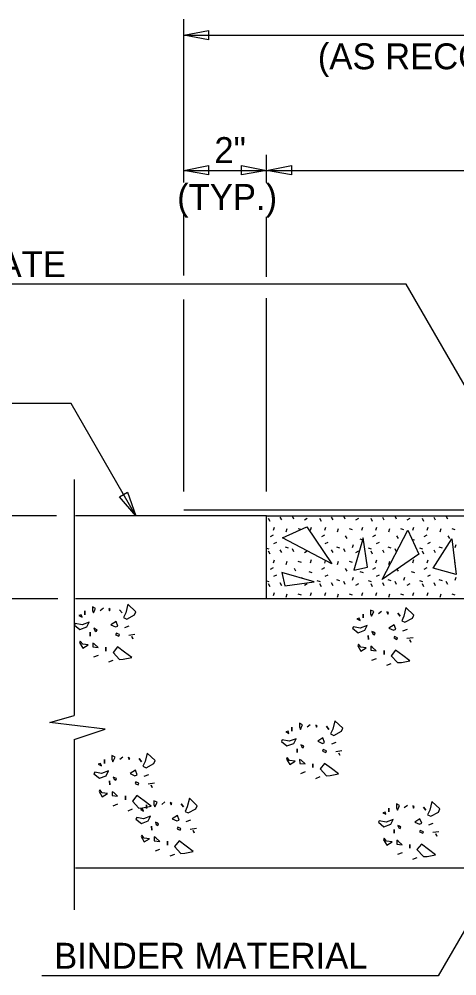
# Model space of a CAD drawing. Extents: x 0 to 11.3, y 0 to 7.8.
# Drawn here: x 2.009 to 2.89, y 1.64 to 3.565 of the extents above; entities that cross this region are included whole.
import ezdxf

# ---------------------------------------------------------------- set-up
doc = ezdxf.new("R2010")
doc.units = 0
for name, color, linetype in [('BRDG_ANNO_General-Notes', 7, 'Continuous'), ('BRDG_BASE_Obj-Line', 7, 'Continuous'), ('BRDG_BASE_Pattern', 7, 'Continuous')]:
    doc.layers.add(name, color=color, linetype=linetype)

msp = doc.modelspace()

# ---------------------------------------------------------------- linework, layer by layer
at = {"layer": 'BRDG_ANNO_General-Notes'}
for p, q in [((2.3401, 3.2366), (2.3401, 3.5652)), ((2.3401, 3.5326), (2.3901, 3.542)), ((2.3401, 3.5326), (4.3401, 3.5326)), ((2.3901, 3.5232), (2.3401, 3.5326)), ((2.3901, 3.542), (2.3901, 3.5232)), ((2.5067, 3.2366), (2.5067, 3.2919)), ((2.3401, 3.2609), (2.3901, 3.2703)), ((2.3401, 3.2609), (2.5067, 3.2609)), ((2.3901, 3.2516), (2.3401, 3.2609)), ((2.3901, 3.2703), (2.3901, 3.2516)), ((2.4567, 3.2516), (2.4567, 3.2703)), ((2.4567, 3.2703), (2.5067, 3.2609)), ((2.5067, 3.2609), (2.4567, 3.2516)), ((2.5067, 3.2609), (2.5567, 3.2703)), ((2.5067, 3.2609), (4.1734, 3.2609)), ((2.5567, 3.2516), (2.5067, 3.2609)), ((2.5567, 3.2703), (2.5567, 3.2516)), ((2.3401, 3.0491), (2.3401, 3.1718)), ((2.5067, 3.0464), (2.5067, 3.1674)), ((2.788, 3.0317), (1.4643, 3.0317)), ((3.1414, 2.4195), (2.788, 3.0317)), ((2.5067, 2.6145), (2.5067, 3.0039)), ((2.3401, 2.6145), (2.3401, 3.0012)), ((2.1133, 2.7918), (1.623, 2.7918)), ((2.244, 2.5654), (2.1133, 2.7918)), ((2.2109, 2.604), (2.2271, 2.6133)), ((2.244, 2.5654), (2.2109, 2.604)), ((2.2271, 2.6133), (2.244, 2.5654)), ((2.0841, 2.5654), (1.4941, 2.5654)), ((2.0867, 2.3987), (1.4941, 2.3987)), ((3.2567, 2.3401), (2.8525, 1.6399)), ((2.8525, 1.6399), (2.0544, 1.6399))]:
    msp.add_line(p, q, dxfattribs=at)
at = {"layer": 'BRDG_BASE_Obj-Line'}
for p, q in [((2.1195, 2.6385), (2.1195, 2.164)), ((2.5067, 2.5654), (2.122, 2.5654)), ((4.3401, 2.5769), (2.3401, 2.5769)), ((2.5067, 2.3987), (2.5067, 2.5654)), ((2.5067, 2.5654), (4.1734, 2.5654)), ((2.5095, 2.5654), (2.5112, 2.5648)), ((2.5103, 2.5611), (2.5133, 2.5552)), ((2.5337, 2.5631), (2.5368, 2.5573)), ((2.562, 2.5589), (2.559, 2.5648)), ((2.6127, 2.5654), (2.6144, 2.5648)), ((2.6134, 2.5611), (2.6165, 2.5552)), ((2.6369, 2.5631), (2.6399, 2.5573)), ((2.6652, 2.5589), (2.6622, 2.5648)), ((2.7158, 2.5654), (2.7176, 2.5648)), ((2.7166, 2.5611), (2.7196, 2.5552)), ((2.7401, 2.5631), (2.7431, 2.5573)), ((2.7684, 2.5589), (2.7654, 2.5648)), ((2.819, 2.5654), (2.8207, 2.5648)), ((2.8198, 2.5611), (2.8228, 2.5552)), ((2.8433, 2.5631), (2.8463, 2.5573)), ((2.8716, 2.5589), (2.8685, 2.5648)), ((2.522, 2.5424), (2.5199, 2.5361)), ((2.5888, 2.5602), (2.5829, 2.5572)), ((2.5964, 2.5425), (2.5944, 2.5362)), ((2.6252, 2.5424), (2.6231, 2.5361)), ((2.6919, 2.5602), (2.6861, 2.5572)), ((2.6996, 2.5425), (2.6976, 2.5362)), ((2.7283, 2.5424), (2.7262, 2.5361)), ((2.7951, 2.5602), (2.7893, 2.5572)), ((2.8028, 2.5425), (2.8008, 2.5362)), ((2.8315, 2.5424), (2.8294, 2.5361)), ((2.5199, 2.5265), (2.514, 2.5234)), ((2.5466, 2.5336), (2.5486, 2.5399)), ((2.5758, 2.5379), (2.5706, 2.5396)), ((2.6231, 2.5265), (2.6171, 2.5234)), ((2.6497, 2.5336), (2.6518, 2.5399)), ((2.6691, 2.5198), (2.666, 2.5257)), ((2.6801, 2.5376), (2.6738, 2.5396)), ((2.7262, 2.5265), (2.7203, 2.5234)), ((2.7529, 2.5336), (2.755, 2.5399)), ((2.7722, 2.5198), (2.7692, 2.5257)), ((2.7832, 2.5376), (2.777, 2.5396)), ((2.8294, 2.5265), (2.8235, 2.5234)), ((2.8561, 2.5336), (2.8582, 2.5399)), ((2.8754, 2.5198), (2.8724, 2.5257)), ((2.8864, 2.5376), (2.8802, 2.5396)), ((2.5216, 2.5098), (2.5274, 2.5129)), ((2.5513, 2.5008), (2.5449, 2.5028)), ((2.6247, 2.5098), (2.6306, 2.5129)), ((2.6544, 2.5008), (2.6481, 2.5028)), ((2.6798, 2.5018), (2.6819, 2.5081)), ((2.6948, 2.5191), (2.7004, 2.5173)), ((2.7279, 2.5098), (2.7338, 2.5129)), ((2.7576, 2.5008), (2.7513, 2.5028)), ((2.7995, 2.5186), (2.8043, 2.5171)), ((2.8311, 2.5098), (2.837, 2.5129)), ((2.8608, 2.5008), (2.8545, 2.5028)), ((2.8862, 2.5018), (2.8882, 2.5081)), ((2.5067, 2.5005), (2.5112, 2.4991)), ((2.5103, 2.4954), (2.5133, 2.4894)), ((2.5337, 2.4974), (2.5368, 2.4916)), ((2.562, 2.4931), (2.559, 2.4991)), ((2.5888, 2.4945), (2.5829, 2.4915)), ((2.6369, 2.4974), (2.6399, 2.4916)), ((2.6652, 2.4931), (2.6622, 2.4991)), ((2.6919, 2.4945), (2.6861, 2.4915)), ((2.7112, 2.5011), (2.7176, 2.4991)), ((2.7166, 2.4954), (2.7196, 2.4894)), ((2.7401, 2.4974), (2.7431, 2.4916)), ((2.7683, 2.4933), (2.7654, 2.4991)), ((2.8144, 2.5011), (2.8207, 2.4991)), ((2.8198, 2.4954), (2.8228, 2.4894)), ((2.8433, 2.4974), (2.8463, 2.4916)), ((2.522, 2.4767), (2.5199, 2.4704)), ((2.5466, 2.4679), (2.5486, 2.4742)), ((2.5769, 2.4719), (2.5706, 2.4739)), ((2.5964, 2.4768), (2.5944, 2.4705)), ((2.6249, 2.4761), (2.6231, 2.4704)), ((2.6497, 2.4679), (2.6518, 2.4742)), ((2.6801, 2.4719), (2.6738, 2.4739)), ((2.7283, 2.4767), (2.7262, 2.4704)), ((2.7529, 2.4679), (2.755, 2.4742)), ((2.8028, 2.4768), (2.8008, 2.4705)), ((2.8315, 2.4767), (2.8294, 2.4704)), ((2.8864, 2.4719), (2.8853, 2.4722)), ((2.5199, 2.4607), (2.514, 2.4577)), ((2.5216, 2.4441), (2.5274, 2.4471)), ((2.5659, 2.4541), (2.5629, 2.4599)), ((2.5916, 2.4534), (2.5979, 2.4514)), ((2.6231, 2.4607), (2.6171, 2.4577)), ((2.6247, 2.4441), (2.6306, 2.4471)), ((2.6691, 2.4541), (2.666, 2.4599)), ((2.6948, 2.4534), (2.7011, 2.4514)), ((2.7262, 2.4607), (2.7203, 2.4577)), ((2.7279, 2.4441), (2.7338, 2.4471)), ((2.7722, 2.4541), (2.7699, 2.4586)), ((2.798, 2.4534), (2.8043, 2.4514)), ((2.8294, 2.4607), (2.8235, 2.4577)), ((2.8311, 2.4441), (2.837, 2.4471)), ((2.5067, 2.4348), (2.5112, 2.4333)), ((2.5103, 2.4296), (2.5133, 2.4237)), ((2.5337, 2.4317), (2.5368, 2.4258)), ((2.5779, 2.44), (2.5787, 2.4423)), ((2.5888, 2.4287), (2.5829, 2.4257)), ((2.6081, 2.4354), (2.6144, 2.4333)), ((2.6134, 2.4296), (2.6165, 2.4237)), ((2.6369, 2.4317), (2.6399, 2.4258)), ((2.6544, 2.4351), (2.6481, 2.4371)), ((2.6652, 2.4274), (2.6622, 2.4333)), ((2.6798, 2.436), (2.6819, 2.4423)), ((2.6919, 2.4287), (2.6861, 2.4257)), ((2.7112, 2.4354), (2.7176, 2.4333)), ((2.7166, 2.4296), (2.7196, 2.4237)), ((2.7401, 2.4317), (2.7431, 2.4258)), ((2.7576, 2.4351), (2.7513, 2.4371)), ((2.7684, 2.4274), (2.7654, 2.4333)), ((2.783, 2.436), (2.7851, 2.4423)), ((2.7951, 2.4287), (2.7893, 2.4257)), ((2.8144, 2.4354), (2.8207, 2.4333)), ((2.8198, 2.4296), (2.8228, 2.4237)), ((2.8433, 2.4317), (2.8463, 2.4258)), ((2.8608, 2.4351), (2.8545, 2.4371)), ((2.8716, 2.4274), (2.8685, 2.4333)), ((2.8862, 2.436), (2.8882, 2.4423)), ((2.522, 2.411), (2.5199, 2.4047)), ((2.5466, 2.4021), (2.5486, 2.4084)), ((2.5769, 2.4061), (2.5706, 2.4081)), ((2.5964, 2.411), (2.5944, 2.4048)), ((2.6252, 2.411), (2.6231, 2.4047)), ((2.6497, 2.4021), (2.6518, 2.4084)), ((2.6801, 2.4061), (2.6738, 2.4081)), ((2.6996, 2.411), (2.6976, 2.4048)), ((2.7283, 2.411), (2.7262, 2.4047)), ((2.7529, 2.4021), (2.755, 2.4084)), ((2.7832, 2.4061), (2.777, 2.4081)), ((2.8028, 2.411), (2.8008, 2.4048)), ((2.8315, 2.411), (2.8294, 2.4047)), ((2.8561, 2.4021), (2.8582, 2.4084)), ((2.8864, 2.4061), (2.8802, 2.4081)), ((3.2567, 2.3987), (2.122, 2.3987)), ((2.0709, 2.1501), (2.1195, 2.164)), ((2.182, 2.1362), (2.0709, 2.1501)), ((2.1195, 2.1154), (2.182, 2.1362)), ((2.1195, 2.1154), (2.1195, 1.773)), ((3.2567, 1.857), (2.122, 1.857))]:
    msp.add_line(p, q, dxfattribs=at)
for points in [[(2.5067, 2.5654), (4.1734, 2.5654), (4.1734, 2.3987), (2.5067, 2.3987)], [(2.6381, 2.4693), (2.5388, 2.5211), (2.5877, 2.5433)], [(2.7393, 2.4378), (2.7911, 2.537), (2.8133, 2.4882)], [(2.7015, 2.5212), (2.6826, 2.4562), (2.7099, 2.4625)], [(2.842, 2.4604), (2.8797, 2.5191), (2.8881, 2.4479)], [(2.6023, 2.4329), (2.5374, 2.4518), (2.5436, 2.4245)]]:
    msp.add_lwpolyline(points, close=True, dxfattribs=at)
at = {"layer": 'BRDG_BASE_Pattern'}
for p, q in [((2.1722, 2.3754), (2.1784, 2.3803)), ((2.7319, 2.3689), (2.7381, 2.3737)), ((2.2215, 2.341), (2.2305, 2.3441)), ((2.7812, 2.3345), (2.7902, 2.3376)), ((2.2295, 2.3257), (2.242, 2.3274)), ((2.7892, 2.3192), (2.8017, 2.3209)), ((2.1593, 2.2816), (2.1684, 2.2851)), ((2.1892, 2.2716), (2.1982, 2.2751)), ((2.719, 2.2751), (2.7281, 2.2786)), ((2.7489, 2.2651), (2.7579, 2.2685)), ((2.5887, 2.1411), (2.5949, 2.146)), ((2.638, 2.1068), (2.647, 2.1099)), ((2.2112, 2.0761), (2.2175, 2.081)), ((2.646, 2.0915), (2.6585, 2.0932)), ((2.2606, 2.0418), (2.2696, 2.0449)), ((2.5758, 2.0474), (2.5849, 2.0509)), ((2.6057, 2.0373), (2.6147, 2.0408)), ((2.2685, 2.0265), (2.281, 2.0282)), ((2.1984, 1.9824), (2.2074, 1.9859)), ((2.2958, 1.9851), (2.3021, 1.9899)), ((2.784, 1.9785), (2.7902, 1.9834)), ((2.2283, 1.9723), (2.2373, 1.9758)), ((2.3452, 1.9507), (2.3542, 1.9538)), ((2.8333, 1.9442), (2.8423, 1.9473)), ((2.3531, 1.9354), (2.3656, 1.9371)), ((2.8413, 1.9289), (2.8537, 1.9306)), ((2.283, 1.8913), (2.292, 1.8948)), ((2.7711, 1.8848), (2.7802, 1.8883)), ((2.3129, 1.8812), (2.3219, 1.8847)), ((2.801, 1.8747), (2.81, 1.8782))]:
    msp.add_line(p, q, dxfattribs=at)
for points in [[(2.2236, 2.3705), (2.2191, 2.3611), (2.2257, 2.358), (2.2409, 2.3664), (2.2437, 2.3726), (2.2278, 2.3876)], [(2.1413, 2.3667), (2.1413, 2.3743)], [(2.1566, 2.3751), (2.1583, 2.3702), (2.1614, 2.3764), (2.1628, 2.3795), (2.1566, 2.3827)], [(2.1892, 2.3789), (2.1909, 2.3743), (2.1923, 2.3774), (2.1923, 2.3774), (2.1923, 2.3774), (2.1923, 2.3774), (2.1892, 2.3789), (2.1892, 2.3789)], [(2.2159, 2.3702), (2.2111, 2.3764)], [(2.7163, 2.3685), (2.718, 2.3636), (2.7211, 2.3699), (2.7225, 2.373), (2.7163, 2.3761)], [(2.7489, 2.3723), (2.7506, 2.3678), (2.752, 2.3709), (2.752, 2.3709), (2.752, 2.3709), (2.752, 2.3709), (2.7489, 2.3723), (2.7489, 2.3723)], [(2.7756, 2.3636), (2.7708, 2.3699)], [(2.7833, 2.364), (2.7788, 2.3546), (2.7854, 2.3515), (2.8006, 2.3598), (2.8034, 2.3661), (2.7874, 2.381)], [(2.1201, 2.3459), (2.1312, 2.3368), (2.1451, 2.342), (2.1496, 2.3514), (2.1357, 2.3462), (2.1218, 2.349)], [(2.1291, 2.3649), (2.1354, 2.3618), (2.1336, 2.3664)], [(2.1934, 2.3462), (2.2028, 2.342), (2.2072, 2.3438), (2.2038, 2.3528)], [(2.6888, 2.3584), (2.6951, 2.3553), (2.6933, 2.3598)], [(2.701, 2.3602), (2.701, 2.3678)], [(2.152, 2.3236), (2.1517, 2.3313)], [(2.1611, 2.3347), (2.1642, 2.333), (2.1642, 2.333), (2.1656, 2.3361), (2.1656, 2.3361), (2.1624, 2.3379), (2.1624, 2.3379), (2.1593, 2.3393), (2.1593, 2.3393), (2.1611, 2.3347)], [(2.2062, 2.3251), (2.2093, 2.3236), (2.2107, 2.3268), (2.2107, 2.3268), (2.2076, 2.3282), (2.2076, 2.3282), (2.2045, 2.3295), (2.2045, 2.3295), (2.2045, 2.3295), (2.2031, 2.3264)], [(2.6798, 2.3394), (2.6909, 2.3303), (2.7048, 2.3355), (2.7093, 2.3449), (2.6954, 2.3397), (2.6815, 2.3425)], [(2.7208, 2.3282), (2.7239, 2.3265), (2.7239, 2.3265), (2.7253, 2.3296), (2.7253, 2.3296), (2.7221, 2.3314), (2.7221, 2.3314), (2.719, 2.3328), (2.719, 2.3328), (2.7208, 2.3282)], [(2.7531, 2.3397), (2.7624, 2.3355), (2.7669, 2.3373), (2.7635, 2.3463)], [(2.1305, 2.3105), (2.1371, 2.2997), (2.1476, 2.3063), (2.1368, 2.3077), (2.1319, 2.3136)], [(2.2374, 2.3181), (2.2357, 2.3226)], [(2.7117, 2.3171), (2.7114, 2.3248)], [(2.7659, 2.3185), (2.769, 2.3171), (2.7704, 2.3203), (2.7704, 2.3203), (2.7673, 2.3217), (2.7673, 2.3217), (2.7642, 2.323), (2.7642, 2.323), (2.7642, 2.323), (2.7628, 2.3199)], [(2.7971, 2.3116), (2.7954, 2.3161)], [(2.1572, 2.3018), (2.168, 2.3007), (2.168, 2.3007), (2.1601, 2.308), (2.1569, 2.3097)], [(2.1836, 2.2934), (2.1836, 2.3011)], [(2.1979, 2.2907), (2.2107, 2.2768), (2.2184, 2.2771), (2.2354, 2.2806), (2.2211, 2.2914), (2.2069, 2.3018)], [(2.6902, 2.304), (2.6968, 2.2932), (2.7072, 2.2998), (2.6965, 2.3011), (2.6916, 2.3071)], [(2.7169, 2.2953), (2.7277, 2.2942), (2.7277, 2.2942), (2.7197, 2.3015), (2.7166, 2.3032)], [(2.7433, 2.2869), (2.7433, 2.2946)], [(2.7576, 2.2842), (2.7704, 2.2703), (2.7781, 2.2706), (2.7951, 2.2741), (2.7808, 2.2848), (2.7666, 2.2953)], [(2.5578, 2.1325), (2.5578, 2.1401)], [(2.5731, 2.1408), (2.5748, 2.1359), (2.5779, 2.1422), (2.5793, 2.1453), (2.5731, 2.1484)], [(2.6057, 2.1446), (2.6074, 2.1401), (2.6089, 2.1432), (2.6089, 2.1432), (2.6089, 2.1432), (2.6089, 2.1432), (2.6057, 2.1446), (2.6057, 2.1446)], [(2.6324, 2.1359), (2.6276, 2.1422)], [(2.6401, 2.1363), (2.6356, 2.1269), (2.6422, 2.1238), (2.6574, 2.1321), (2.6602, 2.1384), (2.6443, 2.1533)], [(2.5456, 2.1307), (2.5519, 2.1276), (2.5502, 2.1321)], [(2.6099, 2.112), (2.6193, 2.1078), (2.6237, 2.1096), (2.6203, 2.1186)], [(2.5366, 2.1117), (2.5477, 2.1026), (2.5616, 2.1078), (2.5661, 2.1172), (2.5522, 2.112), (2.5383, 2.1148)], [(2.5776, 2.1005), (2.5807, 2.0988), (2.5807, 2.0988), (2.5821, 2.1019), (2.5821, 2.1019), (2.579, 2.1036), (2.579, 2.1036), (2.5758, 2.1051), (2.5758, 2.1051), (2.5776, 2.1005)], [(2.1956, 2.0758), (2.1973, 2.0709), (2.2005, 2.0772), (2.2019, 2.0803), (2.1956, 2.0834)], [(2.2283, 2.0796), (2.23, 2.0751), (2.2314, 2.0782), (2.2314, 2.0782), (2.2314, 2.0782), (2.2314, 2.0782), (2.2283, 2.0796), (2.2283, 2.0796)], [(2.2627, 2.0713), (2.2581, 2.0619), (2.2647, 2.0588), (2.28, 2.0671), (2.2828, 2.0734), (2.2668, 2.0883)], [(2.547, 2.0762), (2.5536, 2.0655), (2.5641, 2.0721), (2.5533, 2.0734), (2.5484, 2.0794)], [(2.5685, 2.0894), (2.5682, 2.0971)], [(2.6227, 2.0908), (2.6258, 2.0894), (2.6272, 2.0926), (2.6272, 2.0926), (2.6241, 2.094), (2.6241, 2.094), (2.621, 2.0953), (2.621, 2.0953), (2.621, 2.0953), (2.6196, 2.0922)], [(2.654, 2.0839), (2.6522, 2.0884)], [(2.1682, 2.0657), (2.1744, 2.0626), (2.1727, 2.0671)], [(2.1804, 2.0675), (2.1804, 2.0751)], [(2.255, 2.0709), (2.2502, 2.0772)], [(2.5737, 2.0676), (2.5845, 2.0665), (2.5845, 2.0665), (2.5766, 2.0738), (2.5734, 2.0755)], [(2.6002, 2.0592), (2.6002, 2.0669)], [(2.6144, 2.0565), (2.6272, 2.0426), (2.6349, 2.0429), (2.6519, 2.0464), (2.6377, 2.0571), (2.6234, 2.0676)], [(2.1592, 2.0467), (2.1703, 2.0376), (2.1842, 2.0428), (2.1887, 2.0522), (2.1748, 2.047), (2.1609, 2.0498)], [(2.2324, 2.047), (2.2418, 2.0428), (2.2463, 2.0446), (2.2429, 2.0536)], [(2.1911, 2.0244), (2.1908, 2.0321)], [(2.2002, 2.0355), (2.2033, 2.0338), (2.2033, 2.0338), (2.2046, 2.0369), (2.2046, 2.0369), (2.2015, 2.0386), (2.2015, 2.0386), (2.1984, 2.0401), (2.1984, 2.0401), (2.2002, 2.0355)], [(2.2453, 2.0258), (2.2484, 2.0244), (2.2498, 2.0276), (2.2498, 2.0276), (2.2467, 2.029), (2.2467, 2.029), (2.2435, 2.0303), (2.2435, 2.0303), (2.2435, 2.0303), (2.2421, 2.0272)], [(2.2765, 2.0189), (2.2748, 2.0234)], [(2.1696, 2.0112), (2.1762, 2.0005), (2.1866, 2.0071), (2.1758, 2.0084), (2.171, 2.0144)], [(2.1963, 2.0026), (2.2071, 2.0015), (2.2071, 2.0015), (2.1991, 2.0088), (2.196, 2.0105)], [(2.2369, 1.9915), (2.2498, 1.9776), (2.2574, 1.9779), (2.2744, 1.9814), (2.2602, 1.9921), (2.246, 2.0026)], [(2.2227, 1.9942), (2.2227, 2.0019)], [(2.2649, 1.9764), (2.2649, 1.984)], [(2.2802, 1.9847), (2.2819, 1.9798), (2.2851, 1.9861), (2.2865, 1.9892), (2.2802, 1.9923)], [(2.3129, 1.9885), (2.3146, 1.984), (2.316, 1.9871), (2.316, 1.9871), (2.316, 1.9871), (2.316, 1.9871), (2.3129, 1.9885), (2.3129, 1.9885)], [(2.3396, 1.9798), (2.3347, 1.9861)], [(2.3472, 1.9802), (2.3427, 1.9708), (2.3493, 1.9677), (2.3646, 1.976), (2.3673, 1.9823), (2.3514, 1.9972)], [(2.7683, 1.9782), (2.7701, 1.9733), (2.7732, 1.9796), (2.7746, 1.9827), (2.7683, 1.9858)], [(2.8354, 1.9737), (2.8308, 1.9643), (2.8374, 1.9612), (2.8527, 1.9695), (2.8555, 1.9758), (2.8395, 1.9907)], [(2.2528, 1.9746), (2.259, 1.9715), (2.2573, 1.976)], [(2.7409, 1.9681), (2.7471, 1.965), (2.7454, 1.9695)], [(2.7531, 1.9699), (2.7531, 1.9775)], [(2.801, 1.982), (2.8027, 1.9775), (2.8041, 1.9806), (2.8041, 1.9806), (2.8041, 1.9806), (2.8041, 1.9806), (2.801, 1.982), (2.801, 1.982)], [(2.8277, 1.9733), (2.8229, 1.9796)], [(2.2437, 1.9556), (2.2548, 1.9465), (2.2687, 1.9517), (2.2733, 1.9611), (2.2594, 1.9559), (2.2455, 1.9587)], [(2.2847, 1.9444), (2.2879, 1.9427), (2.2879, 1.9427), (2.2892, 1.9458), (2.2892, 1.9458), (2.2861, 1.9476), (2.2861, 1.9476), (2.283, 1.949), (2.283, 1.949), (2.2847, 1.9444)], [(2.317, 1.9559), (2.3264, 1.9517), (2.3309, 1.9535), (2.3274, 1.9625)], [(2.7319, 1.9491), (2.743, 1.94), (2.7569, 1.9452), (2.7614, 1.9546), (2.7475, 1.9494), (2.7336, 1.9522)], [(2.8052, 1.9494), (2.8145, 1.9452), (2.819, 1.947), (2.8156, 1.956)], [(2.2757, 1.9333), (2.2754, 1.941)], [(2.3298, 1.9347), (2.333, 1.9333), (2.3344, 1.9365), (2.3344, 1.9365), (2.3312, 1.9379), (2.3312, 1.9379), (2.3281, 1.9392), (2.3281, 1.9392), (2.3281, 1.9392), (2.3267, 1.9361)], [(2.3611, 1.9278), (2.3594, 1.9323)], [(2.7638, 1.9268), (2.7635, 1.9345)], [(2.7729, 1.9379), (2.776, 1.9362), (2.776, 1.9362), (2.7773, 1.9393), (2.7773, 1.9393), (2.7742, 1.941), (2.7742, 1.941), (2.7711, 1.9424), (2.7711, 1.9424), (2.7729, 1.9379)], [(2.818, 1.9282), (2.8211, 1.9268), (2.8225, 1.9299), (2.8225, 1.9299), (2.8194, 1.9314), (2.8194, 1.9314), (2.8162, 1.9327), (2.8162, 1.9327), (2.8162, 1.9327), (2.8148, 1.9296)], [(2.8492, 1.9212), (2.8475, 1.9258)], [(2.2542, 1.9202), (2.2608, 1.9094), (2.2712, 1.916), (2.2604, 1.9173), (2.2556, 1.9233)], [(2.2809, 1.9115), (2.2917, 1.9104), (2.2917, 1.9104), (2.2837, 1.9177), (2.2806, 1.9194)], [(2.3073, 1.9031), (2.3073, 1.9108)], [(2.3215, 1.9004), (2.3344, 1.8865), (2.342, 1.8868), (2.359, 1.8903), (2.3448, 1.901), (2.3306, 1.9115)], [(2.7423, 1.9136), (2.7489, 1.9029), (2.7593, 1.9095), (2.7485, 1.9108), (2.7437, 1.9168)], [(2.769, 1.9049), (2.7798, 1.9039), (2.7798, 1.9039), (2.7718, 1.9112), (2.7687, 1.9129)], [(2.7954, 1.8966), (2.7954, 1.9043)], [(2.8096, 1.8939), (2.8225, 1.8799), (2.8302, 1.8803), (2.8471, 1.8838), (2.8329, 1.8945), (2.8187, 1.9049)]]:
    msp.add_lwpolyline(points, close=True, dxfattribs=at)

# ---------------------------------------------------------------- texts
at = {"layer": 'BRDG_ANNO_General-Notes'}
for s, height, p in [('(AS RECOMMENDED BY MANUFACTURER)', 0.052083, (2.61, 3.4643)), ('2"', 0.05208, (2.4018, 3.2756)), ('(TYP.)', 0.05208, (2.3269, 3.1813)), ('BRIDGING PLATE', 0.052083, (1.5186, 3.046)), ('BINDER MATERIAL', 0.052083, (2.0793, 1.6544))]:
    msp.add_text(s, height=height, dxfattribs=at).set_placement(p)

doc.saveas('drawing.dxf')
